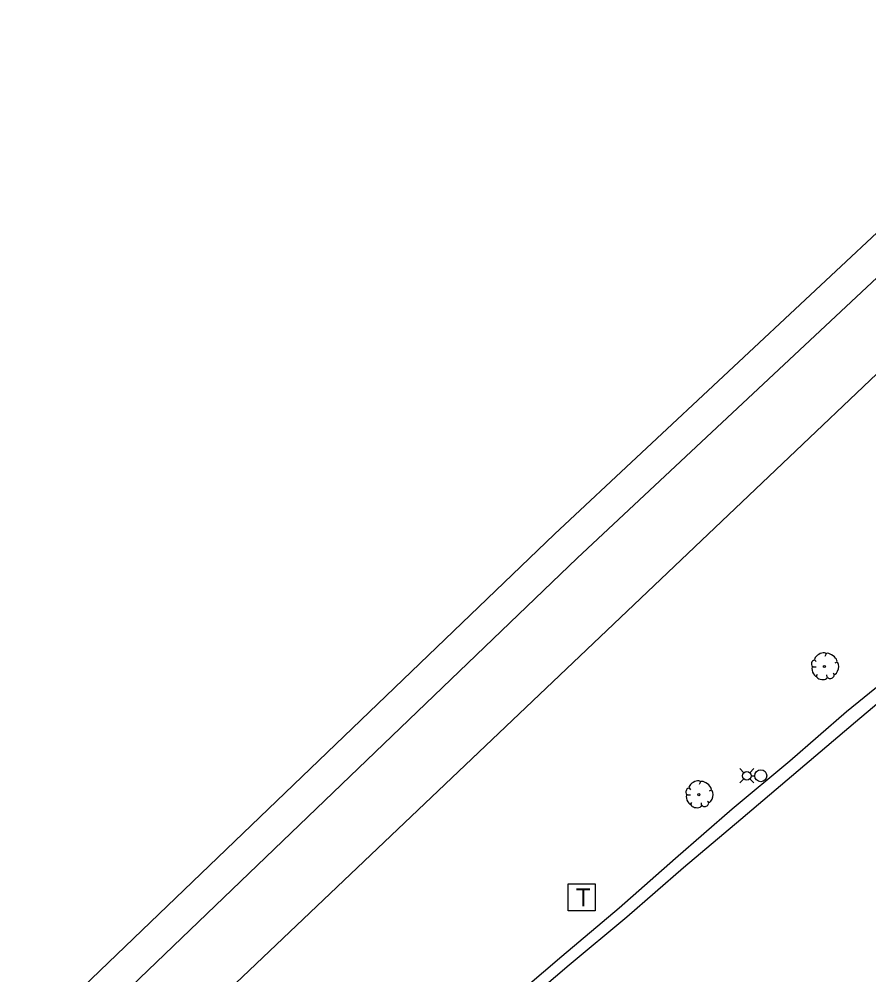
# Model space of a CAD drawing. Extents: x 1042086 to 1119166, y 1916606 to 1927565.
# Drawn here: x 1042832.5 to 1043115.4, y 1926533.5 to 1926851.6 of the extents above; entities that cross this region are included whole.
import ezdxf

# ---------------------------------------------------------------- set-up
doc = ezdxf.new("R2010")
doc.units = 0
for name, color, linetype in [('R_No Plot', 7, 'Continuous'), ('S_EDGE_CONCRETE', 7, 'Continuous'), ('S_SHOULDER', 7, 'Continuous'), ('S_TELEPHONE_UTILITIES', 7, 'Continuous'), ('S_TREE', 7, 'Continuous'), ('S_UTILITY_POLE', 7, 'Continuous')]:
    doc.layers.add(name, color=color, linetype=linetype)

msp = doc.modelspace()

# ---------------------------------------------------------------- linework, layer by layer
at = {"layer": 'R_No Plot'}
for points in [[(1044190.35, 1927564.54), (1043981.84, 1927438.75), (1043847.5, 1927351.11), (1043782.09, 1927308.44), (1043697.07, 1927249.19), (1043570.31, 1927157.92), (1043487.46, 1927093.8), (1043395.3, 1927021.04), (1043346.81, 1926980.95), (1043282.61, 1926927.86), (1043155.48, 1926815.57), (1043010.71, 1926680.15), (1042651.83, 1926335.68), (1042368.92, 1926064.14), (1042086.02, 1925792.6)], [(1044196.03, 1927555.13), (1043987.69, 1927429.43), (1043853.51, 1927341.9), (1043788.24, 1927299.32), (1043703.43, 1927240.21), (1043576.89, 1927149.1), (1043494.23, 1927085.13), (1043402.21, 1927012.49), (1043353.82, 1926972.48), (1043289.76, 1926919.5), (1043162.88, 1926807.43), (1043018.28, 1926672.16), (1042659.44, 1926327.74), (1042376.54, 1926056.21), (1042093.64, 1925784.67)], [(1042478.4, 1926119.04), (1042593.51, 1926230.8), (1042805.67, 1926436.78), (1043162.99, 1926776.23), (1043224.64, 1926831.91), (1043251.28, 1926855.08), (1043316.64, 1926911.14), (1043414.38, 1926992.32), (1043498.45, 1927058.67), (1043606.9, 1927141.54), (1043742.89, 1927238.47), (1043809.93, 1927284.87), (1043730.4, 1927218.11), (1043687.56, 1927181.41)]]:
    msp.add_lwpolyline(points, dxfattribs=at)
at = {"layer": 'S_EDGE_CONCRETE'}
msp.add_lwpolyline([(1042911.59, 1926420.57), (1042897.9, 1926435.96), (1042900.77, 1926438.95), (1042919.78, 1926455.34), (1042939.53, 1926471.89), (1042958.48, 1926488.19), (1042977.65, 1926504.25), (1042996.58, 1926520.57), (1043015.53, 1926536.87), (1043034.78, 1926552.83), (1043053.68, 1926569.19), (1043072.77, 1926585.33), (1043091.84, 1926601.49), (1043110.9, 1926617.67), (1043129.98, 1926633.83), (1043149.08, 1926649.95), (1043168.09, 1926666.19), (1043187.12, 1926682.4), (1043206.26, 1926698.48), (1043225.26, 1926714.73), (1043244.49, 1926730.7), (1043263.56, 1926746.87), (1043281.72, 1926763.08)], dxfattribs=at)
at = {"layer": 'S_SHOULDER'}
msp.add_lwpolyline([(1042898.35, 1926441.3), (1042916.65, 1926458.38), (1042936.71, 1926475.14), (1042955.64, 1926491.46), (1042974.65, 1926507.71), (1042994.08, 1926523.45), (1043013.1, 1926539.67), (1043032.23, 1926555.77), (1043051, 1926572.28), (1043069.8, 1926588.75), (1043089.02, 1926604.75), (1043107.89, 1926621.14), (1043127.31, 1926636.9), (1043146.59, 1926652.82), (1043165.47, 1926669.21), (1043184.66, 1926685.24), (1043203.58, 1926701.57), (1043222.63, 1926717.76), (1043241.64, 1926733.98), (1043260.43, 1926750.48), (1043279.67, 1926765.43), (1043290.38, 1926775.16)], dxfattribs=at)
at = {"layer": 'S_TELEPHONE_UTILITIES'}
msp.add_lwpolyline([(1043015.27, 1926554.76), (1043015.27, 1926563.76), (1043024.27, 1926563.76), (1043024.27, 1926554.76)], close=True, dxfattribs=at)
at = {"layer": 'S_TREE'}
for p, q in [((1043101.11, 1926640.34), (1043100.72, 1926639.48)), ((1043097.31, 1926638.32), (1043097.81, 1926637.74)), ((1043104.67, 1926637.55), (1043104.01, 1926637.27)), ((1043096.65, 1926636), (1043097.78, 1926636)), ((1043097.81, 1926632.82), (1043098.28, 1926633.52)), ((1043101.5, 1926632.55), (1043101.42, 1926633.32)), ((1043103.9, 1926633.44), (1043103.43, 1926633.86)), ((1043059.3, 1926597.71), (1043058.91, 1926596.86)), ((1043054.84, 1926593.37), (1043055.96, 1926593.37)), ((1043055.5, 1926595.7), (1043056, 1926595.12)), ((1043062.86, 1926594.92), (1043062.2, 1926594.65)), ((1043056, 1926590.2), (1043056.47, 1926590.89)), ((1043059.68, 1926589.92), (1043059.61, 1926590.7)), ((1043062.09, 1926590.82), (1043061.62, 1926591.24))]:
    msp.add_line(p, q, dxfattribs=at)
for centre in [(1043100.55, 1926636.09), (1043058.74, 1926593.47)]:
    msp.add_circle(centre, 0.341, dxfattribs=at)
for centre, major_axis, ratio, start_param, end_param in [((1043099.21, 1926639.29), (1.86, 1.08), 0.471018, 0, 3.141593), ((1043102.87, 1926638.97), (-1.81, 1.36), 0.405113, 3.141593, 6.283186), ((1043096.98, 1926637.18), (0.31, 1.03), 0.646762, 0, 3.141593), ((1043104.22, 1926635.56), (0.46, 2.04), 0.482994, 3.141593, 6.283185), ((1043097.29, 1926634.53), (-0.61, 1.6), 0.420543, 6.283185, 9.424777), ((1043099.75, 1926632.75), (-1.83, 0.19), 0.529943, 0, 3.141593), ((1043102.7, 1926633.04), (1.09, 0.46), 0.711534, 3.141592, 6.283185), ((1043057.4, 1926596.67), (1.86, 1.08), 0.471018, 0, 3.141593), ((1043061.06, 1926596.35), (-1.81, 1.36), 0.405113, 3.141593, 6.283186), ((1043055.17, 1926594.56), (0.31, 1.03), 0.646762, 0, 3.141593), ((1043055.47, 1926591.9), (-0.61, 1.6), 0.420543, 6.283185, 9.424777), ((1043062.41, 1926592.94), (0.46, 2.04), 0.482994, 3.141593, 6.283185), ((1043057.93, 1926590.12), (-1.83, 0.19), 0.529943, 0, 3.141593), ((1043060.89, 1926590.42), (1.09, 0.46), 0.711534, 3.141592, 6.283185)]:
    msp.add_ellipse(centre, major_axis=major_axis, ratio=ratio, start_param=start_param, end_param=end_param, dxfattribs=at)
at = {"layer": 'S_UTILITY_POLE'}
for p, q in [((1043073.72, 1926600.78), (1043072.35, 1926602.15)), ((1043075.74, 1926600.78), (1043077.11, 1926602.15)), ((1043076.16, 1926599.77), (1043077.38, 1926599.77)), ((1043072.35, 1926597.4), (1043073.72, 1926598.76)), ((1043077.11, 1926597.4), (1043075.74, 1926598.76))]:
    msp.add_line(p, q, dxfattribs=at)
for centre, radius in [((1043074.73, 1926599.77), 1.43), ((1043079.38, 1926599.77), 2)]:
    msp.add_circle(centre, radius, dxfattribs=at)

# ---------------------------------------------------------------- texts
at = {"layer": 'S_TELEPHONE_UTILITIES'}
msp.add_text('T', height=6, rotation=360, dxfattribs=at).set_placement((1043017.84, 1926556.26))

doc.saveas('drawing.dxf')
